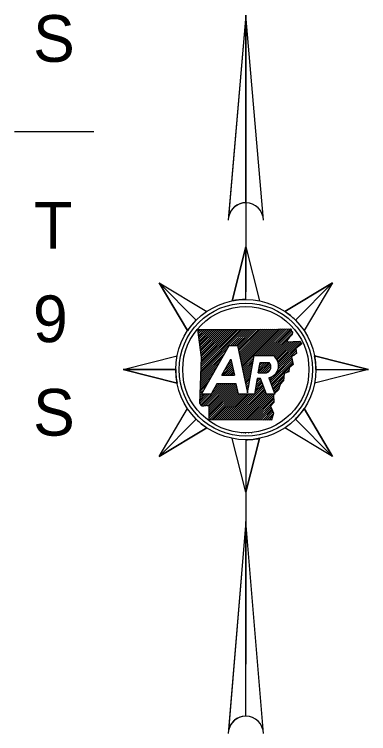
# Model space of a CAD drawing. Extents: x 79818 to 83933, y 50884 to 53307.
# Drawn here: x 83026.1 to 83177.6, y 51402.8 to 51710.7 of the extents above; entities that cross this region are included whole.
import ezdxf

# ---------------------------------------------------------------- set-up
doc = ezdxf.new("R2010")
doc.units = 0
for name, color, linetype in [('Default', 7, 'Continuous'), ('R_Draft', 7, 'Continuous'), ('R_Water Annot', 7, 'Continuous')]:
    doc.layers.add(name, color=color, linetype=linetype)

msp = doc.modelspace()

# ---------------------------------------------------------------- linework, layer by layer
at = {"layer": 'Default'}
msp.add_line((83060.11, 51660.35), (83026.11, 51660.35), dxfattribs=at)
msp.add_line((83060.11, 51660.35), (83026.11, 51660.35), dxfattribs=at)
at = {"layer": 'R_Draft'}
for p, q in [((83125.08, 51710.31), (83117.69, 51623.84)), ((83125.08, 51710.31), (83125.08, 51591.88)), ((83125.08, 51630.06), (83125.08, 51710.31)), ((83117.8, 51625.04), (83118.13, 51625.38)), ((83117.84, 51625.51), (83118.52, 51626.19)), ((83125.08, 51611.1), (83119.24, 51588.03)), ((83125.08, 51588.6), (83125.08, 51611.1)), ((83087.96, 51595.73), (83103.87, 51579.82)), ((83103.87, 51579.82), (83087.96, 51595.73)), ((83087.96, 51595.73), (83100.15, 51575.28)), ((83162.21, 51595.73), (83141.76, 51583.54)), ((83146.3, 51579.82), (83162.21, 51595.73)), ((83146.3, 51579.82), (83162.21, 51595.73)), ((83106.14, 51548.1), (83117.97, 51569)), ((83117.97, 51569), (83121.49, 51569)), ((83114.84, 51556.3), (83118.72, 51563.14)), ((83128.63, 51564.64), (83136.85, 51564.64)), ((83177.58, 51558.6), (83154.51, 51564.45)), ((83131.19, 51561.69), (83135.05, 51561.69)), ((83072.58, 51558.6), (83095.08, 51558.6)), ((83095.08, 51558.6), (83072.58, 51558.6)), ((83072.58, 51558.6), (83095.66, 51552.76)), ((83130.41, 51557.22), (83133.94, 51557.22)), ((83155.08, 51558.6), (83177.58, 51558.6)), ((83155.08, 51558.6), (83177.58, 51558.6)), ((83114.84, 51556.3), (83120.18, 51556.3)), ((83131.41, 51554.74), (83129.98, 51554.74)), ((83133.86, 51548.1), (83131.41, 51554.74)), ((83134.89, 51555.1), (83137.47, 51548.1)), ((83112.68, 51552.48), (83110.2, 51548.1)), ((83121, 51552.48), (83112.68, 51552.48)), ((83110.2, 51548.1), (83106.14, 51548.1)), ((83128.82, 51548.1), (83121.94, 51548.1)), ((83137.47, 51548.1), (83133.86, 51548.1)), ((83162.21, 51521.48), (83150.02, 51541.93)), ((83087.96, 51521.48), (83103.87, 51537.39)), ((83103.87, 51537.39), (83087.96, 51521.48)), ((83146.3, 51537.39), (83162.21, 51521.48)), ((83146.3, 51537.39), (83162.21, 51521.48)), ((83087.96, 51521.48), (83108.41, 51533.67)), ((83125.08, 51506.1), (83130.93, 51529.18)), ((83125.08, 51528.6), (83125.08, 51528.61)), ((83125.08, 51528.6), (83125.08, 51432.57)), ((83125.08, 51528.6), (83125.08, 51506.1)), ((83125.08, 51493.56), (83117.69, 51404.05)), ((83125.08, 51410.31), (83125.08, 51493.56))]:
    msp.add_line(p, q, dxfattribs=at)
for points in [[(83132.58, 51622.56), (83125.08, 51710.31), (83117.58, 51622.56)], [(83119.24, 51588.03), (83125.08, 51611.1), (83130.93, 51588.03)], [(83100.15, 51575.28), (83087.96, 51595.73), (83108.41, 51583.54)], [(83141.76, 51583.54), (83162.21, 51595.73), (83150.02, 51575.28)], [(83104.6, 51575.78), (83116.31, 51575.77), (83126.58, 51575.79), (83138.7, 51575.98), (83144.32, 51576.11)], [(83105.45, 51544.1), (83106.1, 51563.75), (83104.6, 51575.78)], [(83121.49, 51569), (83125.85, 51548.65), (83128.63, 51564.64)], [(83148, 51570.73), (83149.01, 51569.67), (83146.48, 51567.6), (83146.76, 51565.5), (83144.59, 51564.07), (83145.33, 51560.85), (83143.66, 51559.33), (83143.51, 51557.67), (83141.48, 51556.94), (83141.17, 51553.82), (83139.71, 51552.25), (83139, 51549.9), (83136.88, 51547.96), (83137.04, 51544.53), (83135.6, 51542.91), (83136.91, 51539.96), (83136, 51537.04)], [(83142.58, 51570.46), (83148.08, 51570.74)], [(83095.66, 51552.76), (83072.58, 51558.6), (83095.66, 51564.45)], [(83118.72, 51563.14), (83120.18, 51556.3)], [(83154.51, 51564.45), (83177.58, 51558.6), (83154.51, 51552.76)], [(83130.41, 51557.22), (83131.19, 51561.69)], [(83129.98, 51554.74), (83128.82, 51548.1)], [(83121.94, 51548.1), (83121, 51552.48)], [(83108.41, 51533.67), (83087.96, 51521.48), (83100.15, 51541.93)], [(83136, 51537.04), (83109.47, 51537.08), (83109.45, 51542.94)], [(83150.02, 51541.93), (83162.21, 51521.48), (83141.76, 51533.67)], [(83130.93, 51529.18), (83125.08, 51506.1), (83119.24, 51529.18)], [(83132.58, 51402.81), (83125.08, 51493.56), (83117.58, 51402.81)]]:
    msp.add_lwpolyline(points, dxfattribs=at)
for radius in [30, 27]:
    msp.add_circle((83125.08, 51558.6), radius, dxfattribs=at)
for centre, radius, start, end in [((83125.08, 51622.56), 7.5, 0, 180), ((83125.08, 51622.56), 7.5, 90, 170.2296), ((83125.08, 51558.6), 30, 90, 101.2291), ((83125.08, 51558.6), 30, 45, 56.2291), ((83125.08, 51558.6), 30, 135, 146.2291), ((83133.79, 51560.3), 5.31, 281.8626, 54.8705), ((83125.08, 51558.6), 30, 0, 11.2291), ((83133.1, 51559.81), 2.72, 288.1268, 43.8902), ((83125.08, 51558.6), 30, 180, 191.2291), ((83125.08, 51558.6), 30, 315, 326.2291), ((83125.08, 51558.6), 30, 225, 236.2291), ((83125.08, 51558.6), 30, 270, 281.2291), ((83125.08, 51402.81), 7.5, 0, 180), ((83125.08, 51402.81), 7.5, 90, 170.5511)]:
    msp.add_arc(centre, radius, start, end, dxfattribs=at)
for points in [[(83144.32, 51576.11), (83144.35, 51575.79), (83144.46, 51575.63), (83144.47, 51575.32), (83144.59, 51575.19), (83144.8, 51575.06), (83144.99, 51574.85), (83145.03, 51574.61), (83144.98, 51574.35), (83144.96, 51574.07), (83144.93, 51573.82), (83144.89, 51573.6), (83144.72, 51573.42), (83144.55, 51573.29), (83144.4, 51573.14), (83144.29, 51572.98), (83144.1, 51572.8), (83143.91, 51572.62), (83143.76, 51572.46), (83143.61, 51572.26), (83143.54, 51572.03), (83143.37, 51571.88), (83143.24, 51571.73), (83143.07, 51571.54), (83142.98, 51571.34), (83142.81, 51571.12), (83142.78, 51570.9), (83142.67, 51570.72), (83142.66, 51570.7)], [(83109.45, 51542.94), (83109.48, 51542.92), (83109.34, 51543.02), (83109.16, 51543.11), (83108.95, 51543.13), (83108.68, 51543.16), (83108.45, 51543.19), (83108.22, 51543.34), (83107.98, 51543.18), (83107.7, 51543.06), (83107.54, 51543.19), (83107.33, 51543.11), (83107.19, 51543.15), (83106.93, 51542.98), (83106.69, 51543.04), (83106.52, 51542.99), (83106.3, 51543), (83106.26, 51543.24), (83106.05, 51543.28), (83105.87, 51543.38), (83105.75, 51543.63), (83105.66, 51543.83), (83105.45, 51544.1)]]:
    msp.add_spline(points, degree=3, dxfattribs=at)
at = {"layer": 'R_Water Annot'}
for p, q in [((83104.63, 51575.51), (83104.9, 51575.78)), ((83104.73, 51574.76), (83105.75, 51575.78)), ((83104.82, 51574), (83106.6, 51575.78)), ((83104.92, 51573.25), (83107.44, 51575.78)), ((83105.01, 51572.49), (83108.29, 51575.78)), ((83105.1, 51571.74), (83109.14, 51575.78)), ((83105.2, 51570.99), (83109.99, 51575.77)), ((83105.29, 51570.23), (83110.84, 51575.77)), ((83105.39, 51569.48), (83111.68, 51575.77)), ((83105.48, 51568.72), (83112.53, 51575.77)), ((83105.57, 51567.97), (83113.38, 51575.77)), ((83105.67, 51567.21), (83114.23, 51575.77)), ((83105.76, 51566.46), (83115.08, 51575.77)), ((83105.86, 51565.7), (83115.92, 51575.77)), ((83105.89, 51557.25), (83124.43, 51575.79)), ((83105.91, 51558.12), (83123.58, 51575.79)), ((83105.94, 51559), (83122.73, 51575.78)), ((83105.95, 51564.95), (83116.77, 51575.77)), ((83105.97, 51559.88), (83121.87, 51575.78)), ((83106, 51560.76), (83121.02, 51575.78)), ((83106.03, 51561.64), (83120.17, 51575.78)), ((83106.04, 51564.19), (83117.62, 51575.77)), ((83106.06, 51562.51), (83119.32, 51575.78)), ((83106.09, 51563.39), (83118.47, 51575.78)), ((83118.49, 51569), (83125.28, 51575.79)), ((83119.33, 51569), (83126.13, 51575.79)), ((83120.18, 51569), (83126.98, 51575.8)), ((83121.03, 51569), (83127.84, 51575.81)), ((83121.56, 51568.68), (83128.71, 51575.83)), ((83121.71, 51567.98), (83129.57, 51575.84)), ((83121.86, 51567.28), (83130.43, 51575.85)), ((83122.01, 51566.58), (83131.29, 51575.87)), ((83122.16, 51565.88), (83132.15, 51575.88)), ((83122.31, 51565.18), (83133.02, 51575.89)), ((83122.46, 51564.49), (83133.88, 51575.91)), ((83122.61, 51563.79), (83134.74, 51575.92)), ((83122.76, 51563.09), (83135.6, 51575.93)), ((83122.91, 51562.39), (83136.46, 51575.95)), ((83123.06, 51561.69), (83137.33, 51575.96)), ((83123.21, 51560.99), (83138.19, 51575.97)), ((83123.35, 51560.29), (83139.05, 51575.99)), ((83123.5, 51559.59), (83139.92, 51576.01)), ((83129.4, 51564.64), (83140.79, 51576.03)), ((83130.25, 51564.64), (83141.66, 51576.05)), ((83131.1, 51564.64), (83142.53, 51576.07)), ((83131.94, 51564.64), (83143.4, 51576.09)), ((83132.79, 51564.64), (83144.26, 51576.11)), ((83133.64, 51564.64), (83144.45, 51575.45)), ((83134.49, 51564.64), (83144.86, 51575.01)), ((83135.34, 51564.64), (83144.97, 51574.27)), ((83136.19, 51564.64), (83143.04, 51571.49)), ((83136.96, 51564.56), (83142.87, 51570.47)), ((83137.42, 51564.18), (83143.76, 51570.52)), ((83137.84, 51563.74), (83144.66, 51570.56)), ((83138.2, 51563.26), (83145.55, 51570.61)), ((83138.52, 51562.73), (83146.45, 51570.66)), ((83138.78, 51562.14), (83147.34, 51570.7)), ((83138.97, 51561.48), (83148.15, 51570.66)), ((83139.09, 51560.75), (83148.54, 51570.21)), ((83148.17, 51568.98), (83148.94, 51569.75)), ((83105.83, 51555.49), (83116.2, 51565.86)), ((83105.86, 51556.37), (83117.31, 51567.82)), ((83138.91, 51558.88), (83146.62, 51566.58)), ((83139.09, 51559.91), (83146.52, 51567.33)), ((83145.66, 51564.78), (83146.71, 51565.83)), ((83105.8, 51554.61), (83115.09, 51563.91)), ((83118.11, 51562.07), (83118.8, 51562.76)), ((83123.65, 51558.89), (83128.47, 51563.71)), ((83123.8, 51558.19), (83128.29, 51562.68)), ((83135.41, 51553.68), (83144.82, 51563.09)), ((83138.18, 51557.29), (83144.66, 51563.78)), ((83105.74, 51552.86), (83112.87, 51559.99)), ((83105.77, 51553.74), (83113.98, 51561.95)), ((83114.89, 51556.3), (83119.25, 51560.66)), ((83115.73, 51556.3), (83119.4, 51559.96)), ((83115.9, 51558.16), (83119.1, 51561.36)), ((83117.01, 51560.12), (83118.95, 51562.06)), ((83123.95, 51557.5), (83128.11, 51561.65)), ((83124.1, 51556.8), (83127.93, 51560.63)), ((83124.25, 51556.1), (83127.75, 51559.6)), ((83130.42, 51557.22), (83134.88, 51561.69)), ((83130.59, 51558.25), (83134.04, 51561.69)), ((83130.77, 51559.27), (83133.19, 51561.69)), ((83130.95, 51560.3), (83132.34, 51561.69)), ((83131.13, 51561.33), (83131.49, 51561.69)), ((83131.27, 51557.22), (83135.36, 51561.31)), ((83132.12, 51557.22), (83135.64, 51560.75)), ((83132.97, 51557.22), (83135.8, 51560.06)), ((83135.64, 51553.06), (83144.98, 51562.4)), ((83135.87, 51552.44), (83145.13, 51561.71)), ((83136.1, 51551.82), (83145.29, 51561.02)), ((83105.71, 51551.98), (83111.77, 51558.04)), ((83116.58, 51556.3), (83119.55, 51559.26)), ((83117.43, 51556.3), (83119.69, 51558.56)), ((83118.28, 51556.3), (83119.84, 51557.86)), ((83119.13, 51556.3), (83119.99, 51557.17)), ((83119.98, 51556.3), (83120.14, 51556.47)), ((83124.4, 51555.4), (83127.57, 51558.57)), ((83124.55, 51554.7), (83127.39, 51557.54)), ((83124.7, 51554), (83127.22, 51556.52)), ((83133.81, 51557.22), (83135.73, 51559.14)), ((83142.39, 51557.27), (83143.58, 51558.46)), ((83105.65, 51550.23), (83109.55, 51554.13)), ((83105.68, 51551.1), (83110.66, 51556.08)), ((83124.85, 51553.3), (83127.04, 51555.49)), ((83125, 51552.6), (83126.86, 51554.46)), ((83125.15, 51551.9), (83126.68, 51553.43)), ((83129.33, 51550.99), (83131.86, 51553.52)), ((83129.51, 51552.02), (83131.63, 51554.14)), ((83129.69, 51553.05), (83131.38, 51554.74)), ((83129.87, 51554.08), (83130.53, 51554.74)), ((83134.95, 51554.92), (83135.21, 51555.18)), ((83135.18, 51554.3), (83136.8, 51555.91)), ((83136.33, 51551.2), (83141.42, 51556.29)), ((83136.56, 51550.58), (83141.32, 51555.35)), ((83136.78, 51549.96), (83141.23, 51554.4)), ((83105.62, 51549.35), (83108.44, 51552.17)), ((83105.78, 51543.56), (83114.7, 51552.48)), ((83106.28, 51543.22), (83115.54, 51552.48)), ((83106.89, 51542.98), (83116.39, 51552.48)), ((83107.9, 51543.14), (83117.24, 51552.48)), ((83108.76, 51543.15), (83118.09, 51552.48)), ((83109.43, 51542.97), (83118.94, 51552.48)), ((83109.45, 51542.15), (83119.79, 51552.48)), ((83109.46, 51541.3), (83120.64, 51552.48)), ((83109.46, 51540.46), (83121.08, 51552.08)), ((83109.46, 51539.61), (83121.23, 51551.38)), ((83109.46, 51538.76), (83121.38, 51550.68)), ((83111.16, 51549.8), (83113.85, 51552.48)), ((83112.27, 51551.75), (83113, 51552.48)), ((83117.95, 51537.07), (83132.55, 51551.66)), ((83118.8, 51537.07), (83132.77, 51551.04)), ((83119.64, 51537.07), (83133, 51550.42)), ((83125.3, 51551.21), (83126.5, 51552.4)), ((83125.45, 51550.51), (83126.32, 51551.38)), ((83125.6, 51549.81), (83126.14, 51550.35)), ((83128.97, 51548.94), (83132.32, 51552.28)), ((83129.15, 51549.96), (83132.09, 51552.9)), ((83137.01, 51549.34), (83139.61, 51551.94)), ((83137.24, 51548.72), (83139.25, 51550.73)), ((83105.46, 51544.1), (83109.46, 51548.1)), ((83105.48, 51544.96), (83108.61, 51548.1)), ((83105.51, 51545.84), (83107.76, 51548.1)), ((83105.54, 51546.72), (83106.92, 51548.1)), ((83105.56, 51547.59), (83106.23, 51548.26)), ((83105.59, 51548.47), (83107.34, 51550.21)), ((83109.46, 51537.92), (83121.53, 51549.98)), ((83109.48, 51537.08), (83121.68, 51549.28)), ((83110.33, 51537.08), (83121.83, 51548.58)), ((83111.17, 51537.08), (83122.19, 51548.1)), ((83112.02, 51537.08), (83123.04, 51548.1)), ((83112.87, 51537.08), (83123.89, 51548.1)), ((83113.71, 51537.08), (83124.73, 51548.1)), ((83114.56, 51537.07), (83125.58, 51548.1)), ((83115.41, 51537.07), (83126.43, 51548.1)), ((83116.26, 51537.07), (83127.28, 51548.1)), ((83117.1, 51537.07), (83128.13, 51548.1)), ((83120.49, 51537.06), (83133.23, 51549.8)), ((83121.34, 51537.06), (83133.46, 51549.18)), ((83122.19, 51537.06), (83133.69, 51548.56)), ((83123.03, 51537.06), (83134.07, 51548.1)), ((83123.88, 51537.06), (83134.92, 51548.1)), ((83124.73, 51537.06), (83135.77, 51548.1)), ((83125.57, 51537.06), (83136.61, 51548.1)), ((83125.75, 51549.11), (83125.96, 51549.32)), ((83126.42, 51537.05), (83136.9, 51547.53)), ((83127.27, 51537.05), (83136.94, 51546.72)), ((83128.12, 51537.05), (83136.97, 51545.91)), ((83128.96, 51537.05), (83137.01, 51545.1)), ((83129.81, 51537.05), (83135.62, 51542.86)), ((83130.66, 51537.05), (83135.88, 51542.27)), ((83131.5, 51537.05), (83136.14, 51541.68)), ((83132.35, 51537.04), (83136.4, 51541.1)), ((83133.2, 51537.04), (83136.67, 51540.51)), ((83134.05, 51537.04), (83136.89, 51539.88)), ((83134.89, 51537.04), (83136.5, 51538.65)), ((83135.74, 51537.04), (83136.12, 51537.42))]:
    msp.add_line(p, q, dxfattribs=at)
msp.add_circle((83125.08, 51558.6), 28.5, dxfattribs=at)

# ---------------------------------------------------------------- texts
at = {"layer": 'Default'}
for s, p in [('S', (83034.1, 51690.35)), ('T', (83034.53, 51610.35)), ('9', (83034.06, 51570.35)), ('S', (83034.1, 51530.35))]:
    msp.add_text(s, height=20, dxfattribs=at).set_placement(p)
at = {"layer": 'R_Draft'}
msp.add_text('DWB 7-27-17', height=0.5833, dxfattribs=at).set_placement((83123.25, 51531.1))

doc.saveas('drawing.dxf')
